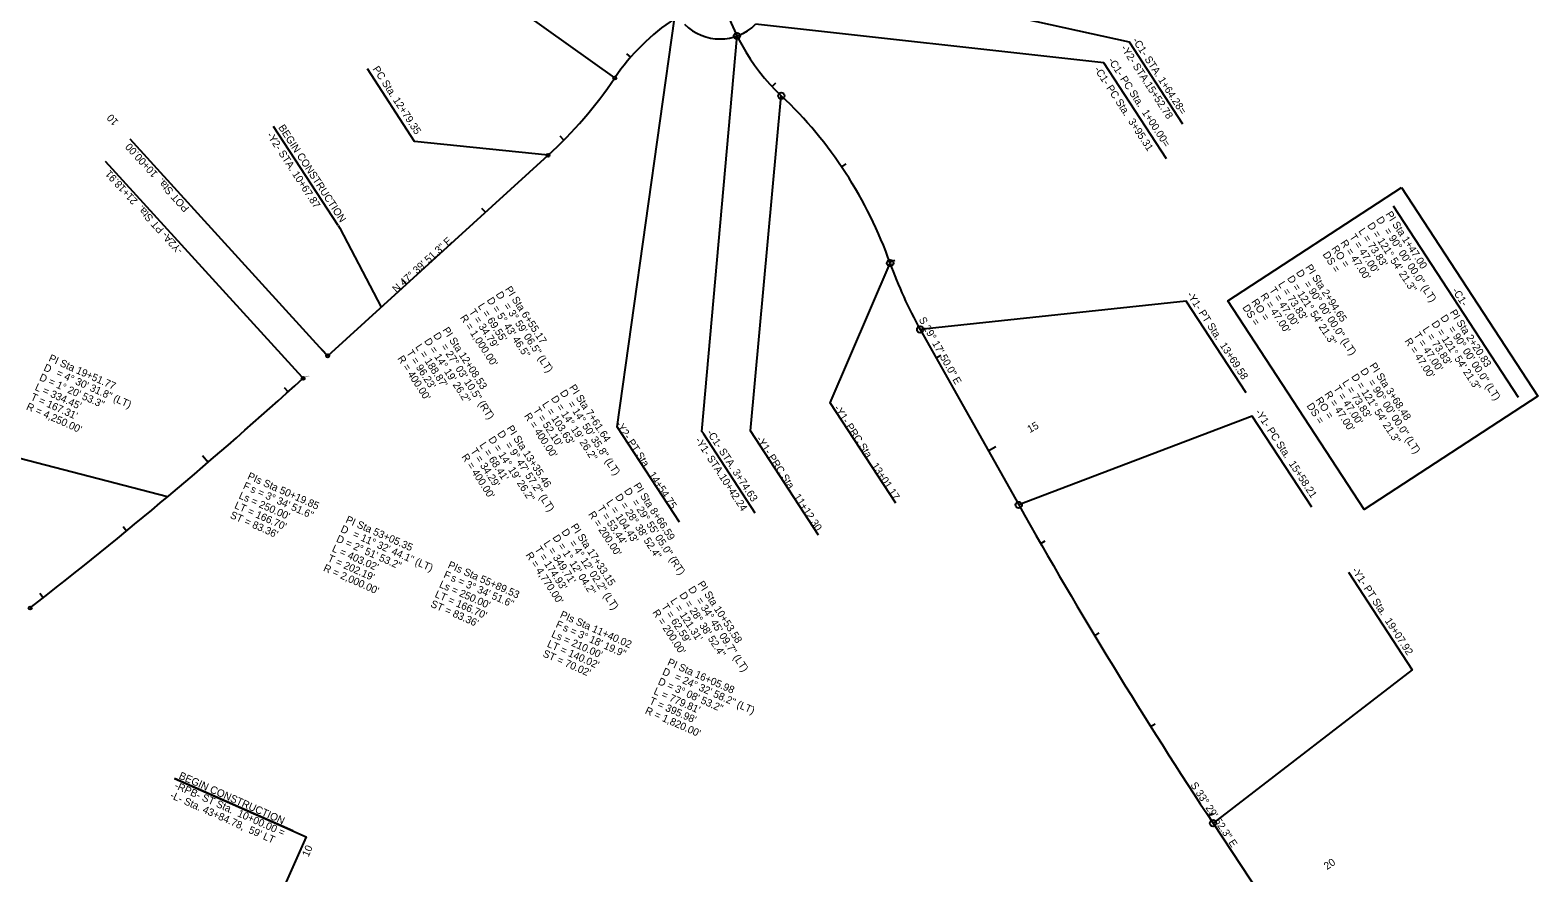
# Model space of a CAD drawing. Extents: x 1636713 to 1642783, y 841520 to 844371.
# Drawn here: x 1639731 to 1641144, y 842918 to 843708 of the extents above; entities that cross this region are included whole.
import ezdxf

# ---------------------------------------------------------------- set-up
doc = ezdxf.new("R2010")
doc.units = 0
for name, color, linetype in [('COGO Default Chain', 7, 'Continuous'), ('Cogo Default Point CELL', 7, 'Continuous'), ('COGO Default Point Number', 7, 'Continuous'), ('Prop Horizontal Alignment', 7, 'Continuous'), ('Prop Horizontal Alignment Curve and Spiral Data', 7, 'Continuous'), ('Prop Horizontal Alignment Direction Label', 7, 'Continuous'), ('Prop Horizontal Alignment Station Label', 7, 'Continuous'), ('Prop Horizontal Alignment Tick Label', 7, 'Continuous'), ('Prop Horizontal Alignment Tick Large', 7, 'Continuous'), ('Prop Horizontal Alignment Tick Small', 7, 'Continuous')]:
    doc.layers.add(name, color=color, linetype=linetype)

msp = doc.modelspace()

# ---------------------------------------------------------------- linework, layer by layer
at = {"layer": 'COGO Default Chain'}
for p, q in [((1640565.4, 843427.4), (1640657.7, 843262.9)), ((1640839.8, 842964.5), (1640951.5, 842795.8))]:
    msp.add_line(p, q, dxfattribs=at)
for centre, radius, start, end in [((1640572.7, 843791.7), 200, 191.7982, 226.5509), ((1640160.1, 843356.2), 400, 19.498, 46.5509), ((1640914.2, 843623.2), 400, 199.498, 209.2972), ((1637124.8, 846523.3), 4250, 307.8269, 312.3357), ((1644817.6, 845597.1), 4770, 209.2972, 213.4979)]:
    msp.add_arc(centre, radius, start, end, dxfattribs=at)
at = {"layer": 'Cogo Default Point CELL'}
for points in [[(1639985.6, 843381.6), (1639987.1, 843381.6)], [(1639987.1, 843383.1), (1639987.1, 843381.6)], [(1639987.1, 843381.6), (1639988.6, 843381.6)], [(1639987.1, 843381.6), (1639987.1, 843380.1)]]:
    msp.add_lwpolyline(points, dxfattribs=at)
msp.add_circle((1639987.1, 843381.6), 1.17, dxfattribs=at)
at = {"layer": 'Prop Horizontal Alignment'}
for p, q in [((1640010.1, 843402.6), (1640216.6, 843590.7)), ((1640565.4, 843427.4), (1640657.7, 843262.9)), ((1640839.8, 842964.5), (1640951.5, 842795.8))]:
    msp.add_line(p, q, dxfattribs=at)
for centre, radius, start, end in [((1640572.7, 843791.7), 200, 191.7982, 226.5509), ((1640445.2, 843551.7), 200, 123.3651, 146.0956), ((1640377.8, 843746.8), 47, 225, 315), ((1639947.2, 843886.4), 400, 312.3357, 326.0956), ((1640160.1, 843356.2), 400, 19.498, 46.5509), ((1640914.2, 843623.2), 400, 199.498, 209.2972), ((1637124.8, 846523.3), 4250, 307.8269, 312.3357), ((1644817.6, 845597.1), 4770, 209.2972, 213.4979)]:
    msp.add_arc(centre, radius, start, end, dxfattribs=at)
at = {"layer": 'Prop Horizontal Alignment Curve and Spiral Data'}
msp.add_line((1641008.6, 843543.4), (1641125.6, 843364), dxfattribs=at)
msp.add_lwpolyline([(1641016.5, 843560.5), (1641144.2, 843364.9), (1640981.4, 843258.7), (1640853.8, 843454.3)], close=True, dxfattribs=at)
at = {"layer": 'Prop Horizontal Alignment Station Label'}
for p, q in [((1640279.2, 843663.2), (1640125.5, 843773.2)), ((1640811.5, 843620), (1640761.4, 843696.8)), ((1640796.2, 843587.3), (1640737.4, 843677.4)), ((1640019.8, 843525), (1639959.3, 843617.7)), ((1640009.1, 843403.7), (1639824.9, 843605.8)), ((1639986.1, 843382.7), (1639801.9, 843584.9)), ((1639986.1, 843382.7), (1639801.9, 843584.9)), ((1640410.7, 843255.2), (1640362.5, 843329.1)), ((1639977.5, 842957.2), (1639866.6, 843006.4))]:
    msp.add_line(p, q, dxfattribs=at)
for points in [[(1640761.4, 843696.8), (1640761.4, 843696.9), (1640417, 843772.6)], [(1640339.8, 843246.6), (1640281.4, 843336.1), (1640335.2, 843718.7)], [(1640737.4, 843677.4), (1640411, 843713.6)], [(1640362.5, 843329.1), (1640360.6, 843331.9), (1640393.7, 843702.6)], [(1640216.6, 843590.7), (1640091.6, 843603.7), (1640047.3, 843671.7)], [(1640470.1, 843234.5), (1640406.3, 843332.3), (1640435.2, 843646.5)], [(1640019.8, 843525), (1640021.6, 843522.3), (1640060.3, 843448.3)], [(1640542.5, 843264.4), (1640480.9, 843358.7), (1640537.2, 843489.7)], [(1640870.7, 843368), (1640814.6, 843454), (1640565.4, 843427.4)], [(1639860, 843270.4), (1639721.5, 843306.5), (1639611.5, 843355.4)], [(1640932.3, 843260.7), (1640876.6, 843346.1), (1640657.7, 843262.9)], [(1640966.6, 843199.8), (1641026.4, 843108.2), (1640839.8, 842964.5)], [(1639866.6, 843006.4), (1639989.8, 842951.8), (1639954.8, 842873)]]:
    msp.add_lwpolyline(points, dxfattribs=at)
for centre, radius in [((1640393.7, 843702.6), 3), ((1640279.2, 843663.2), 1.5), ((1640435.2, 843646.5), 3), ((1640216.6, 843590.7), 1.5), ((1640537.2, 843489.7), 3), ((1640565.4, 843427.4), 3), ((1640010.1, 843402.6), 1.5), ((1640010.1, 843402.6), 1.5), ((1639987.1, 843381.6), 1.5), ((1639987.1, 843381.6), 1.5), ((1640657.7, 843262.9), 3), ((1639731.3, 843166.3), 1.5), ((1640839.8, 842964.5), 3)]:
    msp.add_circle(centre, radius, dxfattribs=at)
at = {"layer": 'Prop Horizontal Alignment Tick Large'}
for p, q in [((1640010.1, 843402.6), (1640004.7, 843408.5)), ((1640010.1, 843402.6), (1640004.7, 843408.5)), ((1640629.2, 843313.7), (1640636.2, 843317.6)), ((1639898.1, 843302.8), (1639892.9, 843308.8))]:
    msp.add_line(p, q, dxfattribs=at)
at = {"layer": 'Prop Horizontal Alignment Tick Small'}
for p, q in [((1640294.1, 843682.8), (1640290.3, 843686)), ((1640426.5, 843655.3), (1640430.2, 843658.7)), ((1640231.5, 843605), (1640227.9, 843608.5)), ((1640491.8, 843579.8), (1640495.9, 843582.6)), ((1640157.9, 843537.3), (1640154.6, 843540.9)), ((1640536.8, 843490.8), (1640541.5, 843492.4)), ((1640084, 843469.9), (1640080.6, 843473.6)), ((1640580.3, 843400.9), (1640584.6, 843403.4)), ((1639973.1, 843368.9), (1639969.7, 843372.6)), ((1639821.6, 843238.4), (1639818.4, 843242.3)), ((1640678.3, 843226.6), (1640682.6, 843229.1)), ((1639743.5, 843175.9), (1639740.4, 843179.8)), ((1640728.9, 843140.3), (1640733.2, 843142.9)), ((1640781.3, 843055.2), (1640785.5, 843057.8)), ((1640835.5, 842971.1), (1640839.6, 842973.9))]:
    msp.add_line(p, q, dxfattribs=at)

# ---------------------------------------------------------------- texts
at = {"layer": 'COGO Default Point Number'}
msp.add_text('15202', height=1.25, dxfattribs=at).set_placement((1639988.3, 843382.9))
at = {"layer": 'Prop Horizontal Alignment Curve and Spiral Data'}
for s, rotation, p in [('D = 121%%d 54\' 21.3"', 303.1259, (1640984, 843525.1)), ('D', 303.1259, (1640992.4, 843530.6)), ('PI Sta 1+47.00', 303.1259, (1641001.2, 843535.5)), ("R = 47.00'", 303.1259, (1640958.9, 843508.7)), ("T = 47.00'", 303.1259, (1640967.3, 843514.2)), ("L = 73.83'", 303.1259, (1640975.7, 843519.7)), ('= 90%%d 00\' 00.0" (LT)', 303.1259, (1640999.7, 843520)), ('DS =', 303.1259, (1640942.2, 843497.8)), ('RO = ', 303.1259, (1640950.5, 843503.3)), ('D', 303.1259, (1640917.3, 843480.8)), ('PI Sta 2+94.65', 303.1259, (1640926, 843485.7)), ("L = 73.83'", 303.1259, (1640900.5, 843469.8)), ('D = 121%%d 54\' 21.3"', 303.1259, (1640908.9, 843475.3)), ('= 90%%d 00\' 00.0" (LT)', 303.1259, (1640924.6, 843470.2)), ('D = 5%%d 43\' 46.5"', 303.1259, (1640158.9, 843454.9)), ('D', 303.1259, (1640167.3, 843460.3)), ('PI Sta 6+55.17', 303.1259, (1640176, 843465.2)), ('RO = ', 303.1259, (1640875.4, 843453.4)), ("R = 47.00'", 303.1259, (1640883.8, 843458.9)), ("T = 47.00'", 303.1259, (1640892.2, 843464.4)), ('-C1-', 303.1259, (1641063.5, 843463.8)), ("R = 1,000.00'", 303.1259, (1640133.8, 843438.5)), ("T = 34.79'", 303.1259, (1640142.2, 843443.9)), ("L = 69.55'", 303.1259, (1640150.5, 843449.4)), ('= 3%%d 59\' 06.5" (LT)', 303.1259, (1640174.6, 843449.7)), ('DS =', 303.1259, (1640867, 843448)), ('D', 303.1259, (1641052.5, 843438.5)), ('PI Sta 2+20.83', 303.1259, (1641061.3, 843443.4)), ('PI Sta 12+08.53', 303.1259, (1640117.4, 843426.9)), ("L = 73.83'", 303.1259, (1641035.8, 843427.5)), ('D = 121%%d 54\' 21.3"', 303.1259, (1641044.2, 843433)), ('= 90%%d 00\' 00.0" (LT)', 303.1259, (1641059.8, 843427.9)), ("L = 188.87'", 303.1259, (1640091.9, 843411.1)), ('D = 14%%d 19\' 26.2"', 303.1259, (1640100.2, 843416.6)), ('D', 303.1259, (1640108.6, 843422)), ('= 27%%d 03\' 10.5" (RT)', 303.1259, (1640115.9, 843411.4)), ("R = 47.00'", 303.1259, (1641019, 843416.6)), ("T = 47.00'", 303.1259, (1641027.4, 843422.1)), ('PI Sta 19+51.77', 335.968, (1639748, 843398.1)), ("R = 400.00'", 303.1259, (1640075.1, 843400.2)), ("T = 96.23'", 303.1259, (1640083.5, 843405.6)), ('D = 1%%d 20\' 53.3"', 335.968, (1639739.2, 843380.1)), ('D', 335.968, (1639743.3, 843389.2)), ('= 4%%d 30\' 31.8" (LT)', 335.968, (1639755.1, 843384.2)), ('D = 121%%d 54\' 21.3"', 303.1259, (1640969, 843383.2)), ('D', 303.1259, (1640977.4, 843388.6)), ('PI Sta 3+68.48', 303.1259, (1640986.1, 843393.5)), ("L = 334.45'", 335.968, (1639735.1, 843370.9)), ('D', 303.1259, (1640227.4, 843368.2)), ('PI Sta 7+61.64', 303.1259, (1640236.1, 843373.1)), ("R = 47.00'", 303.1259, (1640943.9, 843366.8)), ("T = 47.00'", 303.1259, (1640952.3, 843372.2)), ("L = 73.83'", 303.1259, (1640960.6, 843377.7)), ('= 90%%d 00\' 00.0" (LT)', 303.1259, (1640984.7, 843378)), ("R = 4,250.00'", 335.968, (1639727, 843352.7)), ("T = 167.31'", 335.968, (1639731.1, 843361.8)), ("L = 103.63'", 303.1259, (1640210.7, 843357.3)), ('D = 14%%d 19\' 26.2"', 303.1259, (1640219, 843362.7)), ('= 14%%d 50\' 35.8" (LT)', 303.1259, (1640234.7, 843357.6)), ('DS =', 303.1259, (1640927.2, 843355.8)), ('RO = ', 303.1259, (1640935.5, 843361.3)), ("R = 400.00'", 303.1259, (1640193.9, 843346.4)), ("T = 52.10'", 303.1259, (1640202.3, 843351.8)), ('D = 14%%d 19\' 26.2"', 303.1259, (1640160.3, 843324.5)), ('D', 303.1259, (1640168.7, 843329.9)), ('PI Sta 13+35.46', 303.1259, (1640177.5, 843334.8)), ("T = 34.29'", 303.1259, (1640143.6, 843313.5)), ("L = 68.41'", 303.1259, (1640152, 843319)), ('= 9%%d 47\' 57.2" (LT)', 303.1259, (1640176, 843319.3)), ("R = 400.00'", 303.1259, (1640135.2, 843308.1)), ('PIs Sta 50+19.85', 336.0871, (1639934.3, 843287.5)), ("Ls = 250.00'", 336.0871, (1639926.2, 843269.3)), ('F', 336.0871, (1639930.2, 843278.4)), ('s = 3%%d 34\' 51.6"', 336.0871, (1639937.1, 843275.3)), ('D = 28%%d 38\' 52.4"', 303.1259, (1640279.1, 843270.6)), ('D', 303.1259, (1640287.5, 843276.1)), ('PI Sta 8+66.59', 303.1259, (1640296.3, 843281)), ("LT = 166.70'", 336.0871, (1639922.1, 843260.1)), ("R = 200.00'", 303.1259, (1640254, 843254.2)), ("T = 53.44'", 303.1259, (1640262.4, 843259.7)), ("L = 104.43'", 303.1259, (1640270.8, 843265.2)), ('= 29%%d 55\' 05.0" (RT)', 303.1259, (1640294.8, 843265.5)), ("ST = 83.36'", 336.0871, (1639918, 843251)), ('D', 336.0871, (1640021.6, 843237.9)), ('PI Sta 53+05.35', 336.0871, (1640026.3, 843246.7)), ('PI Sta 17+33.15', 303.1259, (1640237.6, 843242.7)), ('D = 2%%d 51\' 53.2"', 336.0871, (1640017.5, 843228.7)), ('= 11%%d 32\' 44.1" (LT)', 336.0871, (1640033, 843233)), ("L = 349.71'", 303.1259, (1640212.1, 843226.9)), ('D = 1%%d 12\' 04.2"', 303.1259, (1640220.5, 843232.3)), ('D', 303.1259, (1640228.8, 843237.8)), ('= 4%%d 12\' 02.2" (LT)', 303.1259, (1640236.1, 843227.2)), ("T = 202.19'", 336.0871, (1640009.4, 843210.4)), ("L = 403.02'", 336.0871, (1640013.5, 843219.6)), ("R = 4,770.00'", 303.1259, (1640195.3, 843215.9)), ("T = 174.93'", 303.1259, (1640203.7, 843221.4)), ("R = 2,000.00'", 336.0871, (1640005.4, 843201.3)), ('F', 336.0871, (1640118.1, 843195.1)), ('PIs Sta 55+89.53', 336.0871, (1640122.1, 843204.2)), ("Ls = 250.00'", 336.0871, (1640114, 843186)), ('s = 3%%d 34\' 51.6"', 336.0871, (1640124.9, 843192.1)), ('D', 303.1259, (1640347.6, 843184)), ('PI Sta 10+53.58', 303.1259, (1640356.4, 843188.9)), ("ST = 83.36'", 336.0871, (1640105.9, 843167.7)), ("LT = 166.70'", 336.0871, (1640109.9, 843176.8)), ("L = 121.31'", 303.1259, (1640330.9, 843173)), ('D = 28%%d 38\' 52.4"', 303.1259, (1640339.3, 843178.5)), ('= 34%%d 45\' 09.7" (LT)', 303.1259, (1640354.9, 843173.4)), ('PIs Sta 11+40.02', 336.0871, (1640227.2, 843157.6)), ("R = 200.00'", 303.1259, (1640314.1, 843162.1)), ("T = 62.59'", 303.1259, (1640322.5, 843167.6)), ("Ls = 210.00'", 336.0871, (1640219.1, 843139.4)), ('F', 336.0871, (1640223.2, 843148.5)), ('s = 3%%d 18\' 19.9"', 336.0871, (1640230, 843145.4)), ("LT = 140.02'", 336.0871, (1640215.1, 843130.2)), ("ST = 70.02'", 336.0871, (1640211, 843121.1)), ('PI Sta 16+05.98', 336.0871, (1640327.8, 843113)), ('D', 336.0871, (1640323.1, 843104.2)), ('= 24%%d 32\' 58.2" (LT)', 336.0871, (1640334.5, 843099.3)), ("L = 779.81'", 336.0871, (1640315, 843085.9)), ('D = 3%%d 08\' 53.2"', 336.0871, (1640319, 843095)), ("R = 1,820.00'", 336.0871, (1640306.9, 843067.6)), ("T = 395.98'", 336.0871, (1640310.9, 843076.8))]:
    msp.add_text(s, height=7, rotation=rotation, dxfattribs=at).set_placement(p)
at = {"layer": 'Prop Horizontal Alignment Direction Label'}
for s, rotation, p in [('N 47%%d 39\' 51.3" E', 42.3357, (1640074.5, 843461.5)), ('S 29%%d 17\' 50.0" E', 299.2972, (1640563.8, 843436.8)), ('S 33%%d 29\' 52.3" E', 303.4979, (1640818.3, 843000.3))]:
    msp.add_text(s, height=7, rotation=rotation, dxfattribs=at).set_placement(p)
at = {"layer": 'Prop Horizontal Alignment Station Label'}
for s, rotation, p in [('-C1- STA. 1+64.28=', 303.1259, (1640763.9, 843698.4)), ('-C1- PC Sta.  1+00.00=', 303.1259, (1640741, 843679.7)), ('-Y2- STA.15+52.78', 303.1259, (1640753.1, 843691.3)), ('PC Sta. 12+79.35', 303.1259, (1640051.9, 843671.6)), ('-C1- PC Sta.  3+95.31', 303.1259, (1640728.1, 843671.3)), ('-Y2- STA. 10+67.87', 303.1259, (1639952.6, 843609.7)), ('BEGIN CONSTRUCTION', 303.1259, (1639963.5, 843616.8)), ('POT Sta.  10+00.00', 132.3357, (1639880.8, 843541.4)), ('-Y2A- PT Sta.  21+18.91', 132.3357, (1639874.9, 843501.8)), ('-Y1- PT Sta.  13+69.58', 303.1259, (1640814.9, 843460)), ('-Y1- PRC Sta.  13+01.17', 303.1259, (1640484.2, 843353.7)), ('-Y1- PC Sta.  15+58.21', 303.1259, (1640878.9, 843349.9)), ('-Y2- PT Sta.  14+54.75', 303.1259, (1640279.6, 843338.8)), ('-C1- STA. 3+74.63', 303.1259, (1640365, 843330.7)), ('-Y1- STA.10+42.24', 303.1259, (1640354.1, 843323.6)), ('-Y1- PRC Sta.  11+12.30', 303.1259, (1640411.3, 843324.7)), ('-Y1- PT Sta.  19+07.92', 303.1259, (1640969.5, 843201.7)), ('BEGIN CONSTRUCTION', 336.0871, (1639870, 843006.6)), ("-L- Sta. 43+84.78,  59' LT", 336.0871, (1639861.8, 842988.3)), ('-RPB- ST Sta.  10+00.00 =', 336.0871, (1639865.9, 842997.4))]:
    msp.add_text(s, height=7, rotation=rotation, dxfattribs=at).set_placement(p)
at = {"layer": 'Prop Horizontal Alignment Tick Label'}
for s, rotation, p in [('10', 132.3357, (1639814.6, 843622.3)), ('10', 132.3357, (1639814.6, 843622.3)), ('15', 29.2972, (1640668.1, 843330.2)), ('10', 66.0871, (1639992.1, 842932.4)), ('20', 33.4979, (1640946.5, 842920.5))]:
    msp.add_text(s, height=7, rotation=rotation, dxfattribs=at).set_placement(p)

doc.saveas('drawing.dxf')
